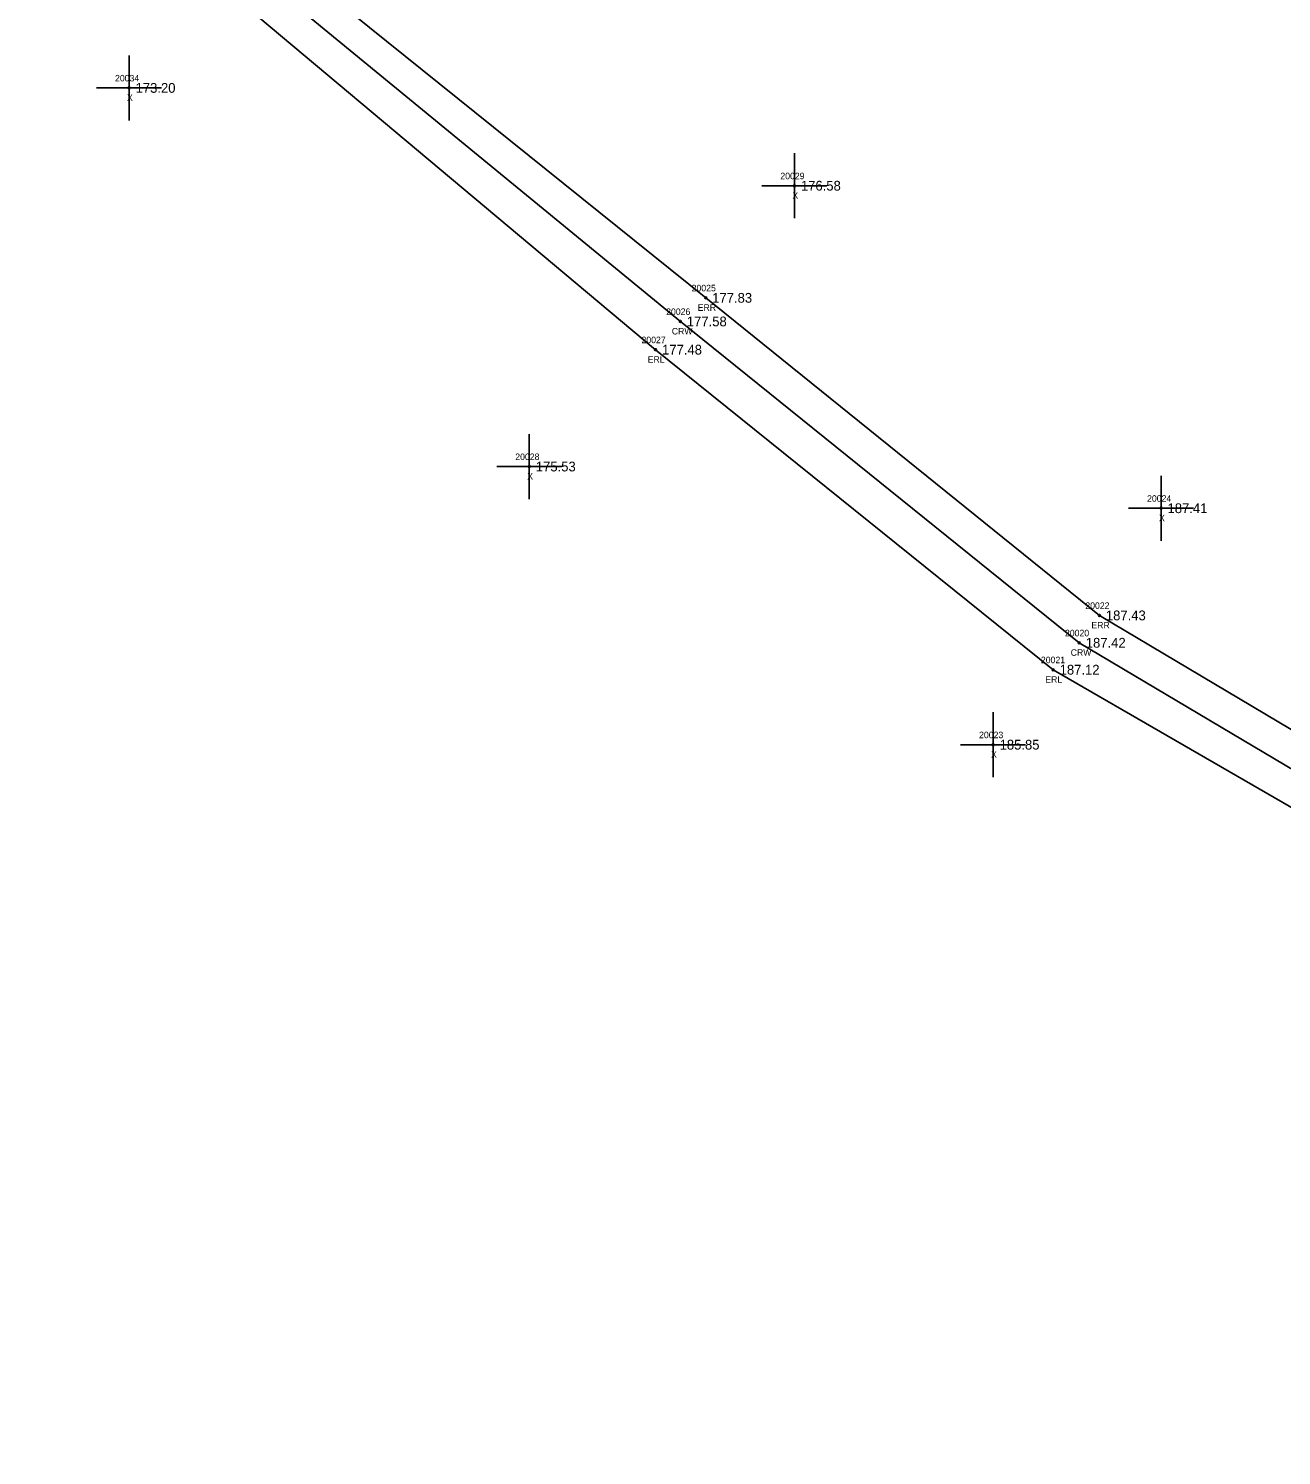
# Model space of a CAD drawing. Extents: x 1970726 to 1971567, y 794829 to 795775.
# Drawn here: x 1971181.9 to 1971374.6, y 794846.6 to 795066 of the extents above; entities that cross this region are included whole.
import ezdxf

# ---------------------------------------------------------------- set-up
doc = ezdxf.new("R2010")
doc.units = 0
for name, color, linetype in [('RD_DTM_BkLn1', 7, 'Continuous'), ('RD_EX_Misc', 7, 'Continuous'), ('RD_EX_Misc_txCode', 7, 'Continuous'), ('RD_EX_Road', 7, 'Continuous'), ('RD_EX_Road_txCode', 7, 'Continuous'), ('RD_EX_TX_Misc_ELEV', 7, 'Continuous'), ('RD_EX_TX_Road_ELEV', 7, 'Continuous'), ('RD_HC_Survey_ELEV', 7, 'Continuous'), ('RD_HC_Survey_txCode', 7, 'Continuous'), ('RD_SMD_Locator', 7, 'Continuous')]:
    doc.layers.add(name, color=color, linetype=linetype)

msp = doc.modelspace()

# ---------------------------------------------------------------- linework, layer by layer
at = {"layer": 'RD_DTM_BkLn1'}
msp.add_lwpolyline([(1971548, 794856.6), (1971469.65, 794899.39), (1971398.6, 794938.78), (1971343.49, 794971.52), (1971282.15, 795020.93), (1971214.82, 795076.24), (1971168.26, 795117.15), (1971077.37, 795216.68), (1971014.25, 795285.1), (1970928, 795384.12), (1970874.41, 795450.05), (1970851.19, 795487.2), (1970834.94, 795528.12), (1970822.6, 795571.11), (1970808.56, 795633.3), (1970801.01, 795695.48), (1970787.01, 795762.98)], dxfattribs=at)
at = {"layer": 'RD_EX_Misc'}
for p, q in [((1971197.39, 795051.84), (1971197.39, 795061.84)), ((1971192.39, 795056.84), (1971202.39, 795056.84)), ((1971299.69, 795036.8), (1971299.69, 795046.8)), ((1971294.69, 795041.8), (1971304.69, 795041.8)), ((1971258.93, 794993.62), (1971258.93, 795003.62)), ((1971253.93, 794998.62), (1971263.93, 794998.62)), ((1971356.06, 794987.21), (1971356.06, 794997.21)), ((1971351.06, 794992.21), (1971361.06, 794992.21)), ((1971330.24, 794950.85), (1971330.24, 794960.85)), ((1971325.24, 794955.85), (1971335.24, 794955.85))]:
    msp.add_line(p, q, dxfattribs=at)
at = {"layer": 'RD_EX_Road'}
for points in [[(1971550.5, 794861.13), (1971472.2, 794904.32), (1971401.49, 794943.08), (1971346.58, 794975.73), (1971286.05, 795024.56), (1971217.92, 795079.41), (1971172.76, 795121.06), (1971082.31, 795221.27), (1971017.96, 795288.13), (1970931.75, 795387.33), (1970878.11, 795452.95), (1970856.35, 795489.48), (1970840.29, 795529.45), (1970827.57, 795574.31), (1970814.81, 795635.62), (1970805.04, 795696.13), (1970791.39, 795763.83)], [(1971543.68, 794851.6), (1971507.7, 794872.08), (1971504.76, 794847.96), (1971494.98, 794846.56), (1971488.18, 794883), (1971469.72, 794893.79), (1971395.92, 794934.76), (1971339.47, 794967.38), (1971278.34, 795016.59), (1971212.1, 795072.1), (1971165.04, 795113.96), (1971074.42, 795213.48), (1971010.42, 795281.48), (1970922.49, 795383.19), (1970882.25, 795365.41), (1970854.66, 795404.07), (1970871.45, 795443.76), (1970844.39, 795483.83), (1970828.93, 795526.65), (1970817.76, 795568.61), (1970806.82, 795600.57), (1970787.72, 795602.49), (1970770.58, 795591.56)]]:
    msp.add_lwpolyline(points, dxfattribs=at)
at = {"layer": 'RD_SMD_Locator'}
for centre in [(1971197.39, 795056.84), (1971299.69, 795041.8), (1971286.05, 795024.56), (1971282.15, 795020.93), (1971278.34, 795016.59), (1971258.93, 794998.62), (1971356.06, 794992.21), (1971346.58, 794975.73), (1971343.49, 794971.52), (1971339.47, 794967.38), (1971330.24, 794955.85)]:
    msp.add_circle(centre, 0.15, dxfattribs=at)

# ---------------------------------------------------------------- texts
at = {"layer": 'RD_EX_Misc_txCode'}
for s, p in [('20034', (1971195.23, 795057.84)), ('X', (1971197.07, 795054.84)), ('20029', (1971297.53, 795042.8)), ('X', (1971299.38, 795039.8)), ('20028', (1971256.77, 794999.62)), ('X', (1971258.61, 794996.62)), ('20024', (1971353.91, 794993.21)), ('X', (1971355.75, 794990.21)), ('20023', (1971328.08, 794956.85)), ('X', (1971329.92, 794953.85))]:
    msp.add_text(s, height=1, dxfattribs=at).set_placement(p)
at = {"layer": 'RD_EX_Road_txCode'}
for s, p in [('20025', (1971283.89, 795025.56)), ('ERR', (1971284.82, 795022.56)), ('20027', (1971276.18, 795017.59)), ('ERL', (1971277.13, 795014.59)), ('20022', (1971344.42, 794976.73)), ('ERR', (1971345.35, 794973.73)), ('20021', (1971337.59, 794968.38)), ('ERL', (1971338.26, 794965.38))]:
    msp.add_text(s, height=1, dxfattribs=at).set_placement(p)
at = {"layer": 'RD_EX_TX_Misc_ELEV'}
for s, p in [('173.20', (1971198.39, 795056.09)), ('176.58', (1971300.69, 795041.05)), ('175.53', (1971259.93, 794997.87)), ('187.41', (1971357.06, 794991.46)), ('185.85', (1971331.24, 794955.1))]:
    msp.add_text(s, height=1.5, dxfattribs=at).set_placement(p)
at = {"layer": 'RD_EX_TX_Road_ELEV'}
for s, p in [('177.83', (1971287.05, 795023.81)), ('177.48', (1971279.34, 795015.84)), ('187.43', (1971347.58, 794974.98)), ('187.12', (1971340.47, 794966.63))]:
    msp.add_text(s, height=1.5, dxfattribs=at).set_placement(p)
at = {"layer": 'RD_HC_Survey_ELEV'}
for s, p in [('177.58', (1971283.15, 795020.18)), ('187.42', (1971344.49, 794970.77))]:
    msp.add_text(s, height=1.5, dxfattribs=at).set_placement(p)
at = {"layer": 'RD_HC_Survey_txCode'}
for s, p in [('20026', (1971279.97, 795021.93)), ('CRW', (1971280.84, 795018.93)), ('20020', (1971341.29, 794972.52)), ('CRW', (1971342.17, 794969.52))]:
    msp.add_text(s, height=1, dxfattribs=at).set_placement(p)

doc.saveas('drawing.dxf')
